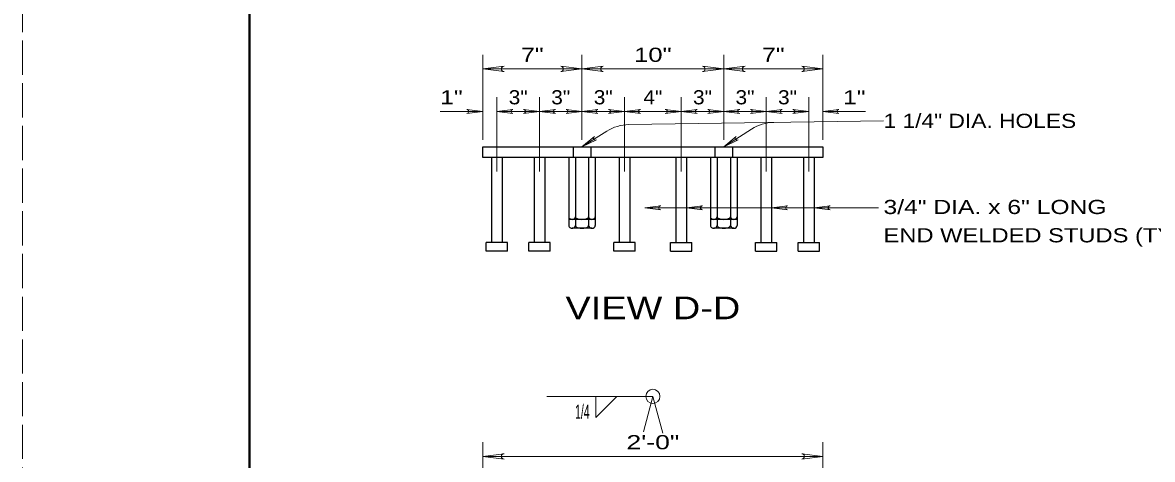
# Model space of a CAD drawing. Extents: x 1285 to 1427, y 1365 to 1427.
# Drawn here: x 1333.33 to 1346.62, y 1375.38 to 1380.52 of the extents above; entities that cross this region are included whole.
import ezdxf
from ezdxf.enums import TextEntityAlignment as Align

# ---------------------------------------------------------------- set-up
doc = ezdxf.new("R2010")
doc.units = 0
doc.header["$LTSCALE"] = 0.067
doc.linetypes.add('LONG_DASHED', pattern=[7.5, 6, -1.5])
for name, color, linetype, lineweight in [('1', 7, 'Continuous', 40), ('42', 7, 'Continuous', 25), ('44', 7, 'Continuous', 13)]:
    doc.layers.add(name, color=color, linetype=linetype, lineweight=lineweight)

msp = doc.modelspace()

# ---------------------------------------------------------------- linework, layer by layer
at = {"layer": '1', "linetype": 'LONG_DASHED', "lineweight": 13}
msp.add_lwpolyline([(1333.33333, 1394.66667), (1378.66667, 1394.66667), (1378.66667, 1365.33333), (1333.33333, 1365.33333)], close=True, dxfattribs=at)
at = {"layer": '1'}
msp.add_lwpolyline([(1336, 1394), (1378, 1394), (1378, 1366), (1336, 1366)], close=True, dxfattribs=at)
at = {"layer": '42', "linetype": 'LONG_DASHED'}
for p, q in [((1339.80622, 1379.05689), (1339.80622, 1378.93189)), ((1340.01456, 1379.05689), (1340.01456, 1378.93189)), ((1341.47278, 1379.05689), (1341.47278, 1378.93189)), ((1341.68111, 1379.05689), (1341.68111, 1378.93189))]:
    msp.add_line(p, q, dxfattribs=at)
at = {"layer": '42'}
for p, q in [((1338.84778, 1378.93189), (1338.84778, 1377.93189)), ((1338.97278, 1378.93189), (1338.97278, 1377.93189)), ((1339.34778, 1378.93189), (1339.34778, 1377.93189)), ((1339.47278, 1378.93189), (1339.47278, 1377.93189)), ((1339.754, 1378.93189), (1339.754, 1378.12978)), ((1339.83211, 1378.93189), (1339.83211, 1378.12978)), ((1339.98856, 1378.93189), (1339.98856, 1378.12978)), ((1340.06667, 1378.93189), (1340.06667, 1378.12978)), ((1340.34778, 1378.93189), (1340.34778, 1377.93189)), ((1340.47278, 1378.93189), (1340.47278, 1377.93189)), ((1341.01456, 1378.93189), (1341.01456, 1377.93189)), ((1341.13956, 1378.93189), (1341.13956, 1377.93189)), ((1341.42067, 1378.93189), (1341.42067, 1378.12978)), ((1341.49878, 1378.93189), (1341.49878, 1378.12978)), ((1341.65522, 1378.93189), (1341.65522, 1378.12978)), ((1341.73333, 1378.93189), (1341.73333, 1378.12978)), ((1342.01456, 1378.93189), (1342.01456, 1377.93189)), ((1342.13956, 1378.93189), (1342.13956, 1377.93189)), ((1342.51456, 1378.93189), (1342.51456, 1377.93189)), ((1342.63956, 1378.93189), (1342.63956, 1377.93189)), ((1340.06667, 1378.20278), (1339.754, 1378.20278)), ((1341.73333, 1378.20278), (1341.42067, 1378.20278)), ((1340.02756, 1378.09856), (1339.793, 1378.09856)), ((1341.69422, 1378.09856), (1341.45967, 1378.09856)), ((1339.03533, 1377.93189), (1338.78533, 1377.93189)), ((1339.03533, 1377.82778), (1339.03533, 1377.93189)), ((1339.53533, 1377.93189), (1339.28533, 1377.93189)), ((1339.53533, 1377.82778), (1339.53533, 1377.93189)), ((1340.53533, 1377.93189), (1340.28533, 1377.93189)), ((1340.53533, 1377.82778), (1340.53533, 1377.93189)), ((1340.952, 1377.82778), (1340.952, 1377.93189)), ((1340.952, 1377.93189), (1341.202, 1377.93189)), ((1341.952, 1377.82778), (1341.952, 1377.93189)), ((1341.952, 1377.93189), (1342.202, 1377.93189)), ((1342.452, 1377.82778), (1342.452, 1377.93189)), ((1342.452, 1377.93189), (1342.702, 1377.93189))]:
    msp.add_line(p, q, dxfattribs=at)
msp.add_lwpolyline([(1338.74367, 1379.05689), (1342.74367, 1379.05689), (1342.74367, 1378.93189), (1338.74367, 1378.93189)], close=True, dxfattribs=at)
for points in [[(1339.03533, 1377.82778), (1338.78533, 1377.82778), (1338.78533, 1377.93189)], [(1339.53533, 1377.82778), (1339.28533, 1377.82778), (1339.28533, 1377.93189)], [(1340.53533, 1377.82778), (1340.28533, 1377.82778), (1340.28533, 1377.93189)], [(1340.952, 1377.82778), (1341.202, 1377.82778), (1341.202, 1377.93189)], [(1341.952, 1377.82778), (1342.202, 1377.82778), (1342.202, 1377.93189)], [(1342.452, 1377.82778), (1342.702, 1377.82778), (1342.702, 1377.93189)]]:
    msp.add_lwpolyline(points, dxfattribs=at)
for centre, major_axis, ratio, start_param, end_param in [((1339.79306, 1378.234), (0.03906, 0), 0.799432, 3.14159265, 6.28318531), ((1339.91033, 1378.234), (0.07822, 0), 0.399148, 3.14159265, 6.28318531), ((1340.02761, 1378.234), (-0.03906, 0), 0.799432, 6.28318531, 9.42477796), ((1341.45972, 1378.234), (0.03906, 0), 0.799432, 3.14159265, 6.28318531), ((1341.577, 1378.234), (0.07822, 0), 0.399148, 3.14159265, 6.28318531), ((1341.69428, 1378.234), (-0.03906, 0), 0.799432, 6.28318531, 9.42477796), ((1339.79306, 1378.12978), (0.03906, 0), 0.799432, 3.14159265, 6.28318531), ((1339.91033, 1378.12978), (0.07822, 0), 0.399148, 3.14159265, 6.28318531), ((1340.02761, 1378.12978), (-0.03906, 0), 0.799432, 6.28318531, 9.42477796), ((1341.45972, 1378.12978), (0.03906, 0), 0.799432, 3.14159265, 6.28318531), ((1341.577, 1378.12978), (0.07822, 0), 0.399148, 3.14159265, 6.28318531), ((1341.69428, 1378.12978), (-0.03906, 0), 0.799432, 6.28318531, 9.42477796)]:
    msp.add_ellipse(centre, major_axis=major_axis, ratio=ratio, start_param=start_param, end_param=end_param, dxfattribs=at)
at = {"layer": '44'}
for p, q in [((1338.74367, 1379.14022), (1338.74367, 1380.14022)), ((1339.91033, 1379.14022), (1339.91033, 1380.14022)), ((1341.577, 1379.14022), (1341.577, 1380.14022)), ((1342.74367, 1379.14022), (1342.74367, 1380.14022)), ((1338.99367, 1380.00478), (1338.74367, 1379.97356)), ((1339.91033, 1379.97356), (1339.66033, 1380.00478)), ((1340.16033, 1380.00478), (1339.91033, 1379.97356)), ((1341.577, 1379.97356), (1341.327, 1380.00478)), ((1341.827, 1380.00478), (1341.577, 1379.97356)), ((1342.74367, 1379.97356), (1342.49367, 1380.00478)), ((1342.49367, 1379.94233), (1342.74367, 1379.97356)), ((1338.91033, 1378.76522), (1338.91033, 1379.64022)), ((1339.41033, 1378.76522), (1339.41033, 1379.64022)), ((1340.41033, 1378.76522), (1340.41033, 1379.64022)), ((1341.077, 1378.76522), (1341.077, 1379.64022)), ((1342.077, 1378.76522), (1342.077, 1379.64022)), ((1342.577, 1378.76522), (1342.577, 1379.64022)), ((1338.74367, 1379.47356), (1338.55622, 1379.497)), ((1339.09778, 1379.497), (1338.91033, 1379.47356)), ((1339.41033, 1379.47356), (1339.22289, 1379.497)), ((1339.59778, 1379.497), (1339.41033, 1379.47356)), ((1339.91033, 1379.47356), (1339.72289, 1379.497)), ((1340.09778, 1379.497), (1339.91033, 1379.47356)), ((1340.41033, 1379.47356), (1340.22289, 1379.497)), ((1340.59778, 1379.497), (1340.41033, 1379.47356)), ((1341.077, 1379.47356), (1340.88956, 1379.497)), ((1341.26444, 1379.497), (1341.077, 1379.47356)), ((1341.577, 1379.47356), (1341.38956, 1379.497)), ((1341.76444, 1379.497), (1341.577, 1379.47356)), ((1342.077, 1379.47356), (1341.88956, 1379.497)), ((1342.26444, 1379.497), (1342.077, 1379.47356)), ((1342.577, 1379.47356), (1342.38956, 1379.497)), ((1342.93111, 1379.497), (1342.74367, 1379.47356)), ((1338.74367, 1379.47356), (1338.24367, 1379.47356)), ((1338.55622, 1379.45011), (1338.74367, 1379.47356)), ((1338.91033, 1379.47356), (1339.09778, 1379.45011)), ((1343.45522, 1379.36256), (1340.46122, 1379.31822)), ((1342.38956, 1379.45011), (1342.577, 1379.47356)), ((1343.24367, 1379.47356), (1342.74367, 1379.47356)), ((1342.74367, 1379.47356), (1342.93111, 1379.45011)), ((1340.20156, 1379.24089), (1339.91033, 1379.05689)), ((1341.577, 1379.05689), (1341.90367, 1379.26511)), ((1340.05633, 1379.17689), (1339.91033, 1379.05689)), ((1339.91033, 1379.05689), (1340.08133, 1379.13722)), ((1341.72256, 1379.17744), (1341.577, 1379.05689)), ((1341.577, 1379.05689), (1341.74767, 1379.13789)), ((1340.83533, 1378.36267), (1340.64789, 1378.33922)), ((1341.327, 1378.36267), (1341.13956, 1378.33922)), ((1341.13956, 1378.33922), (1341.327, 1378.31578)), ((1342.327, 1378.36267), (1342.13956, 1378.33922)), ((1342.13956, 1378.33922), (1342.327, 1378.31578)), ((1342.827, 1378.36267), (1342.63956, 1378.33922)), ((1342.63956, 1378.33922), (1342.827, 1378.31578)), ((1340.74367, 1376.11889), (1339.49767, 1376.11889)), ((1338.74367, 1373.57989), (1338.74367, 1375.57989)), ((1342.74367, 1373.57989), (1342.74367, 1375.57989)), ((1338.99367, 1375.44444), (1338.74367, 1375.41322)), ((1338.74367, 1375.41322), (1342.74367, 1375.41322)), ((1338.74367, 1375.41322), (1338.99367, 1375.382)), ((1342.74367, 1375.41322), (1342.49367, 1375.44444)), ((1342.49367, 1375.382), (1342.74367, 1375.41322))]:
    msp.add_line(p, q, dxfattribs=at)
for points in [[(1339.91033, 1379.97356), (1338.74367, 1379.97356), (1338.99367, 1379.94233)], [(1339.66033, 1379.94233), (1339.91033, 1379.97356), (1340.16033, 1379.94233)], [(1339.91033, 1379.97356), (1341.577, 1379.97356), (1342.74367, 1379.97356)], [(1341.327, 1379.94233), (1341.577, 1379.97356), (1341.827, 1379.94233)], [(1338.91033, 1379.47356), (1339.41033, 1379.47356), (1339.91033, 1379.47356), (1340.41033, 1379.47356), (1341.077, 1379.47356), (1341.577, 1379.47356), (1342.077, 1379.47356), (1342.577, 1379.47356)], [(1339.22289, 1379.45011), (1339.41033, 1379.47356), (1339.59778, 1379.45011)], [(1339.72289, 1379.45011), (1339.91033, 1379.47356), (1340.09778, 1379.45011)], [(1340.22289, 1379.45011), (1340.41033, 1379.47356), (1340.59778, 1379.45011)], [(1340.88956, 1379.45011), (1341.077, 1379.47356), (1341.26444, 1379.45011)], [(1341.38956, 1379.45011), (1341.577, 1379.47356), (1341.76444, 1379.45011)], [(1341.88956, 1379.45011), (1342.077, 1379.47356), (1342.26444, 1379.45011)], [(1343.39578, 1378.33922), (1340.64789, 1378.33922), (1340.83533, 1378.31578)], [(1340.07122, 1376.11889), (1340.07122, 1375.86889), (1340.32122, 1376.11889)], [(1340.63167, 1375.70044), (1340.74367, 1376.11889), (1340.85989, 1375.68467)]]:
    msp.add_lwpolyline(points, dxfattribs=at)
msp.add_circle((1340.74367, 1376.11889), 0.08333, dxfattribs=at)
for centre, radius, start, end in [((1338.99367, 1379.97356), 0.03122, 90, 270), ((1339.66033, 1379.97356), 0.03122, 270, 90), ((1340.16033, 1379.97356), 0.03122, 90, 270), ((1341.327, 1379.97356), 0.03122, 270, 90), ((1341.827, 1379.97356), 0.03122, 90, 270), ((1342.49367, 1379.97356), 0.03122, 270, 90), ((1338.55617, 1379.47356), 0.02342, 270, 90), ((1339.09783, 1379.47356), 0.02342, 90, 270), ((1339.22283, 1379.47356), 0.02342, 270, 90), ((1339.59783, 1379.47356), 0.02342, 90, 270), ((1339.72283, 1379.47356), 0.02342, 270, 90), ((1340.09783, 1379.47356), 0.02342, 90, 270), ((1340.22283, 1379.47356), 0.02342, 270, 90), ((1340.59783, 1379.47356), 0.02342, 90, 270), ((1340.8895, 1379.47356), 0.02342, 270, 90), ((1341.2645, 1379.47356), 0.02342, 90, 270), ((1341.3895, 1379.47356), 0.02342, 270, 90), ((1341.7645, 1379.47356), 0.02342, 90, 270), ((1341.8895, 1379.47356), 0.02342, 270, 90), ((1342.2645, 1379.47356), 0.02342, 90, 270), ((1342.3895, 1379.47356), 0.02342, 270, 90), ((1342.93117, 1379.47356), 0.02342, 90, 270), ((1342.17247, 1378.84351), 0.5, 90.84834, 122.51326), ((1340.46868, 1378.81825), 0.5, 90.84886, 122.28907), ((1340.06885, 1379.15704), 0.02342, 122.28551, 302.28551), ((1341.73511, 1379.15767), 0.02342, 122.51405, 302.51405), ((1340.83539, 1378.33922), 0.02342, 90, 270), ((1341.32706, 1378.33922), 0.02342, 90, 270), ((1342.32706, 1378.33922), 0.02342, 90, 270), ((1342.82706, 1378.33922), 0.02342, 90, 270), ((1338.99367, 1375.41322), 0.03122, 90, 270), ((1342.49367, 1375.41322), 0.03122, 270, 90)]:
    msp.add_arc(centre, radius, start, end, dxfattribs=at)

# ---------------------------------------------------------------- texts
for s, height, width, p in [('7"', 0.1667, 1.3, (1339.32706, 1380.05689)), ('10"', 0.1667, 1.35, (1340.74372, 1380.05689)), ('7"', 0.1667, 1.3, (1342.16039, 1380.05689)), ('3"', 0.1667, 1.1, (1339.16028, 1379.55689)), ('3"', 0.1667, 1.1, (1339.66028, 1379.55689)), ('3"', 0.1667, 1.1, (1340.16028, 1379.55689)), ('4"', 0.1667, 1.1, (1340.74361, 1379.55689)), ('3"', 0.1667, 1.1, (1341.32694, 1379.55689)), ('3"', 0.1667, 1.1, (1341.82694, 1379.55689)), ('3"', 0.1667, 1.1, (1342.32694, 1379.55689)), ('VIEW D-D', 0.2667, 1.25, (1340.74361, 1377.02744)), ('2\'-0"', 0.1667, 1.4, (1340.74372, 1375.49656))]:
    msp.add_text(s, height=height, dxfattribs=dict(at, width=width)).set_placement(p, align=Align.CENTER)
for s, width, p in [('1"', 1.3, (1338.24367, 1379.55689)), ('1 1/4" DIA. HOLES', 1.2, (1343.45522, 1379.27922)), ('3/4" DIA. x 6" LONG', 1.3, (1343.45522, 1378.26556)), ('END WELDED STUDS (TYP.)', 1.25, (1343.45522, 1377.93222))]:
    msp.add_text(s, height=0.1667, dxfattribs=dict(at, width=width)).set_placement(p)
for s, width, p in [('1"', 1.3, (1343.24367, 1379.55689)), ('1/4', 0.55, (1339.99989, 1375.85622))]:
    msp.add_text(s, height=0.1667, dxfattribs=dict(at, width=width)).set_placement(p, align=Align.RIGHT)

doc.saveas('drawing.dxf')
